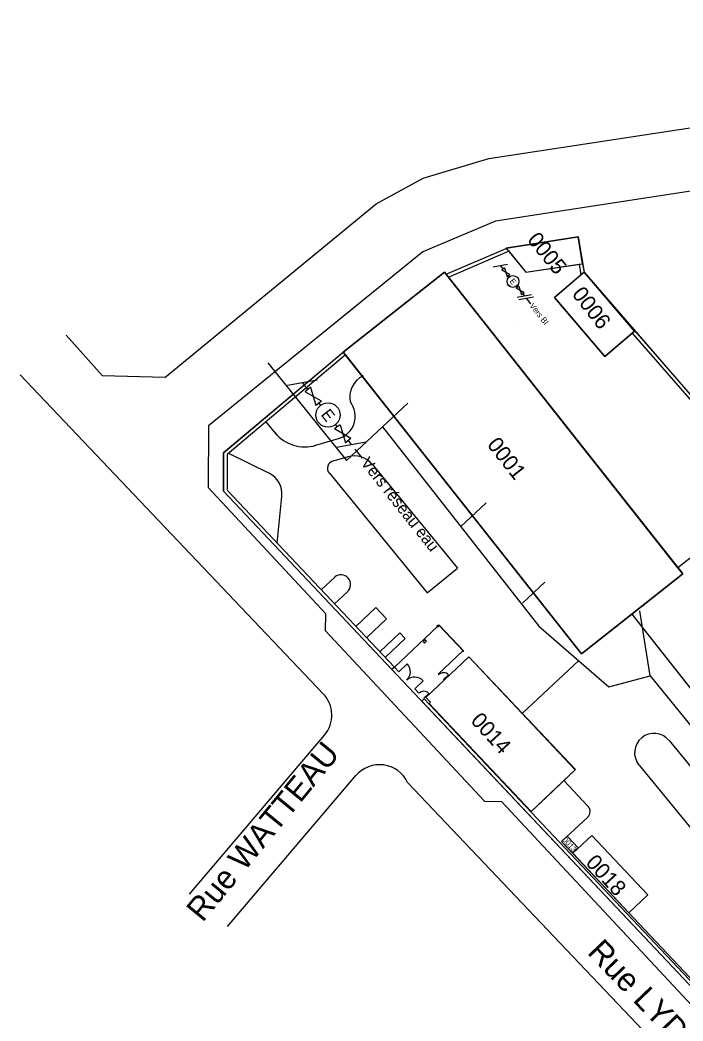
# Model space of a CAD drawing. Extents: x 703432 to 707394, y 7057985 to 7059523.
# Drawn here: x 704151.5 to 704236.8, y 7058728.3 to 7058857.2 of the extents above; entities that cross this region are included whole.
import ezdxf

# ---------------------------------------------------------------- set-up
doc = ezdxf.new("R2010")
doc.units = 0
for name, color, linetype in [('DH_HACHURE-MOTIF', 7, 'Continuous'), ('DH_TEXTE', 7, 'Continuous'), ('GO_MUR_EXTERIEUR', 7, 'Continuous'), ('IMM_LIMITE PHYSIQUE', 7, 'Continuous'), ('R_EPR_AEP_CANALISATION_CL_A', 7, 'Continuous'), ('R_PLU_CANALISATION_CL_A', 7, 'Continuous'), ('RES_EAU BASSE PRESSION', 7, 'Continuous'), ('RES_EAU BASSE PRESSION - EQUIP - TEXTE', 7, 'Continuous'), ('RES_INCENDIE - EQUIP - TEXTE', 7, 'Continuous'), ('SID_NUMERO_BATI', 7, 'Continuous'), ('SID_POLYLIGNES_BATI', 7, 'Continuous'), ('SID_POLYLIGNES_IMMEUBLE', 7, 'Continuous'), ('VOIRIE_BORDURE', 7, 'Continuous'), ('VOIRIE_ROUTE', 7, 'Continuous')]:
    doc.layers.add(name, color=color, linetype=linetype)

msp = doc.modelspace()

# ---------------------------------------------------------------- linework, layer by layer
at = {"layer": 'DH_HACHURE-MOTIF'}
for p, q in [((704220.3, 7058821.49), (704223.72, 7058824.42)), ((704223.72, 7058824.42), (704224.1, 7058824.74)), ((704224.1, 7058824.74), (704230.6, 7058817.15)), ((704226.8, 7058813.9), (704220.3, 7058821.49))]:
    msp.add_line(p, q, dxfattribs=at)
for points in [[(704223.47, 7058825.75), (704223.92, 7058825.82), (704223.34, 7058829.27), (704214.07, 7058827.84), (704214.4, 7058827.44), (704216.62, 7058824.72), (704223.47, 7058825.75)], [(704193.39, 7058814.1), (704195.59, 7058811.31), (704223.77, 7058775.59), (704230.25, 7058780.7), (704236.81, 7058785.87), (704236.19, 7058786.66), (704206.45, 7058824.35), (704206.14, 7058824.73), (704193.11, 7058814.45), (704193.39, 7058814.1)], [(704230.6, 7058817.15), (704230.26, 7058816.85), (704226.8, 7058813.9)], [(704282.57, 7058740.22), (704242.19, 7058791.4), (704236.19, 7058786.66), (704236.81, 7058785.87), (704230.25, 7058780.7), (704270.01, 7058730.31), (704282.57, 7058740.22)], [(704222.01, 7058752.02), (704221.94, 7058752.09), (704221.22, 7058751.41), (704222.64, 7058749.9), (704223.36, 7058750.59), (704222.01, 7058752.02)]]:
    msp.add_lwpolyline(points, dxfattribs=at)
for points in [[(704219.26, 7058757.12), (704222.98, 7058760.63), (704209.26, 7058775.18), (704203.74, 7058769.97), (704204.32, 7058769.36), (704204.15, 7058769.2), (704217.3, 7058755.27)], [(704225.09, 7058752.21), (704222.64, 7058749.9), (704229.88, 7058742.22), (704232.33, 7058744.54)]]:
    msp.add_lwpolyline(points, close=True, dxfattribs=at)
at = {"layer": 'GO_MUR_EXTERIEUR'}
for p, q in [((704223.34, 7058829.27), (704214.07, 7058827.84)), ((704223.92, 7058825.82), (704223.34, 7058829.27)), ((704214.07, 7058827.84), (704216.62, 7058824.72)), ((704216.62, 7058824.72), (704223.92, 7058825.82)), ((704193.11, 7058814.45), (704206.14, 7058824.73)), ((704206.14, 7058824.73), (704236.81, 7058785.87)), ((704224.1, 7058824.74), (704220.3, 7058821.49)), ((704230.6, 7058817.15), (704224.1, 7058824.74)), ((704220.3, 7058821.49), (704226.8, 7058813.9)), ((704220.3, 7058821.49), (704220.3, 7058821.49)), ((704226.8, 7058813.9), (704230.6, 7058817.15)), ((704223.77, 7058775.59), (704193.11, 7058814.45)), ((704242.19, 7058791.4), (704236.19, 7058786.66)), ((704236.19, 7058786.66), (704236.81, 7058785.87)), ((704236.81, 7058785.87), (704223.77, 7058775.59)), ((704236.81, 7058785.87), (704230.25, 7058780.7)), ((704230.25, 7058780.7), (704270.01, 7058730.31)), ((704209.29, 7058775.21), (704203.74, 7058769.97)), ((704223.02, 7058760.67), (704209.29, 7058775.21)), ((704217.3, 7058755.27), (704223.02, 7058760.67)), ((704221.22, 7058751.41), (704221.94, 7058752.09)), ((704221.94, 7058752.09), (704223.36, 7058750.59)), ((704222.64, 7058749.9), (704221.22, 7058751.41)), ((704223.36, 7058750.59), (704222.64, 7058749.9))]:
    msp.add_line(p, q, dxfattribs=at)
msp.add_lwpolyline([(704203.74, 7058769.97), (704204.32, 7058769.36), (704204.15, 7058769.2), (704217.3, 7058755.27)], dxfattribs=at)
msp.add_lwpolyline([(704225.09, 7058752.21), (704232.33, 7058744.54), (704229.88, 7058742.22), (704222.64, 7058749.9)], close=True, dxfattribs=at)
at = {"layer": 'IMM_LIMITE PHYSIQUE'}
for p, q in [((704206.36, 7058824.47), (704214.09, 7058827.8)), ((704206.66, 7058824.11), (704214.39, 7058827.45)), ((704223.47, 7058825.75), (704223.7, 7058824.4)), ((704223.92, 7058825.82), (704224.1, 7058824.74)), ((704230.31, 7058816.9), (704242.05, 7058803.37)), ((704230.65, 7058817.19), (704242.2, 7058803.87)), ((704193.12, 7058814.45), (704177.69, 7058801.47)), ((704193.4, 7058814.1), (704178.14, 7058801.27)), ((704177.69, 7058801.47), (704177.69, 7058796.52)), ((704178.14, 7058801.27), (704178.14, 7058796.73)), ((704177.69, 7058796.52), (704199.36, 7058773.55)), ((704178.16, 7058796.68), (704199.69, 7058773.86)), ((704199.69, 7058773.86), (704205.25, 7058779.11)), ((704205.34, 7058772.97), (704208.55, 7058776)), ((704199.69, 7058773.86), (704199.36, 7058773.55)), ((704199.69, 7058773.86), (704200.24, 7058773.28)), ((704200.24, 7058773.28), (704201.33, 7058774.3)), ((704205.34, 7058772.97), (704205.39, 7058772.91)), ((704206.67, 7058772.87), (704206.01, 7058772.26)), ((704206.01, 7058772.26), (704206.07, 7058772.19)), ((704202.3, 7058771.09), (704203.39, 7058772.12)), ((704202.3, 7058771.09), (704202.85, 7058770.51)), ((704203.53, 7058769.79), (704203.2, 7058769.48)), ((704204.12, 7058770.47), (704203.47, 7058769.86)), ((704203.47, 7058769.86), (704203.53, 7058769.79)), ((704203.53, 7058769.79), (704267.13, 7058702.37)), ((704203.2, 7058769.48), (704266.9, 7058701.96))]:
    msp.add_line(p, q, dxfattribs=at)
for points in [[(704205.41, 7058779.26), (704205.17, 7058779.2), (704205.33, 7058779.02)], [(704205.41, 7058779.26), (704208.57, 7058775.91), (704208.61, 7058775.94), (704205.45, 7058779.29)], [(704203.37, 7058777.19), (704203.58, 7058776.98), (704203.82, 7058777.2), (704203.62, 7058777.42)]]:
    msp.add_lwpolyline(points, close=True, dxfattribs=at)
for centre, radius, start, end in [((704200.24, 7058773.28), 1.5, 313.3307, 43.3307), ((704202.3, 7058771.09), 1.5, 43.3307, 133.3307), ((704206.01, 7058772.26), 0.9, 43.3307, 133.3307), ((704203.47, 7058769.86), 0.9, 43.3307, 133.3307)]:
    msp.add_arc(centre, radius, start, end, dxfattribs=at)
at = {"layer": 'R_EPR_AEP_CANALISATION_CL_A'}
for p, q in [((704183.39, 7058813.05), (704193.51, 7058800.5)), ((704198.15, 7058804.83), (704201.43, 7058807.89)), ((704193.51, 7058800.5), (704198.15, 7058804.83)), ((704198.15, 7058804.83), (704218.29, 7058779.15)), ((704208.22, 7058791.99), (704211.5, 7058795.05)), ((704216.18, 7058782.12), (704219.07, 7058784.82)), ((704232.63, 7058772.76), (704231.28, 7058781.12)), ((704216.16, 7058767.94), (704223.43, 7058774.72))]:
    msp.add_line(p, q, dxfattribs=at)
msp.add_lwpolyline([(704218.29, 7058779.15), (704227.29, 7058771.34), (704232.63, 7058772.76), (704273.17, 7058722.82)], dxfattribs=at)
at = {"layer": 'R_PLU_CANALISATION_CL_A'}
msp.add_circle((704214.95, 7058823.54), 0.76, dxfattribs=at)
at = {"layer": 'RES_EAU BASSE PRESSION'}
for p, q in [((704185.93, 7058810.19), (704189.75, 7058810.87)), ((704189.94, 7058807.86), (704190.18, 7058807.57)), ((704192.34, 7058804.83), (704192.11, 7058805.12)), ((704192.23, 7058802.21), (704196.05, 7058802.88)), ((704193.73, 7058803.06), (704194.14, 7058802.54))]:
    msp.add_line(p, q, dxfattribs=at)
at = {"layer": 'RES_EAU BASSE PRESSION - EQUIP - TEXTE'}
for p, q in [((704188.55, 7058809.63), (704187.84, 7058810.53)), ((704188.9, 7058809.91), (704188.2, 7058809.35)), ((704188.9, 7058809.91), (704189.59, 7058807.58)), ((704190.3, 7058808.14), (704188.2, 7058809.35)), ((704190.3, 7058808.14), (704189.59, 7058807.58)), ((704192.69, 7058805.1), (704191.99, 7058804.55)), ((704194.09, 7058803.34), (704191.99, 7058804.55)), ((704192.69, 7058805.1), (704193.38, 7058802.78)), ((704194.09, 7058803.34), (704193.38, 7058802.78)), ((704194.6, 7058801.95), (704195.53, 7058800.78))]:
    msp.add_line(p, q, dxfattribs=at)
msp.add_circle((704191.14, 7058806.34), 1.56, dxfattribs=at)
at = {"layer": 'RES_INCENDIE - EQUIP - TEXTE'}
for p, q in [((704212.4, 7058825.42), (704214.27, 7058825.75)), ((704213.68, 7058825.15), (704213.33, 7058825.59)), ((704213.85, 7058825.28), (704213.51, 7058825.01)), ((704213.85, 7058825.28), (704214.19, 7058824.15)), ((704214.54, 7058824.42), (704213.51, 7058825.01)), ((704214.54, 7058824.42), (704214.19, 7058824.15)), ((704214.36, 7058824.28), (704214.48, 7058824.14)), ((704215.71, 7058822.93), (704215.36, 7058822.66)), ((704216.39, 7058822.07), (704215.36, 7058822.66)), ((704215.53, 7058822.8), (704215.42, 7058822.94)), ((704215.71, 7058822.93), (704216.04, 7058821.8)), ((704215.48, 7058821.51), (704217.35, 7058821.85)), ((704215.71, 7058821.23), (704217.58, 7058821.56)), ((704216.39, 7058822.07), (704216.04, 7058821.8)), ((704216.22, 7058821.93), (704216.42, 7058821.68)), ((704216.64, 7058821.39), (704217.21, 7058820.67)), ((704215.49, 7058818.53), (704215.49, 7058818.53))]:
    msp.add_line(p, q, dxfattribs=at)
msp.add_circle((704214.95, 7058823.54), 0.763, dxfattribs=at)
at = {"layer": 'SID_POLYLIGNES_BATI'}
for p, q in [((704223.34, 7058829.27), (704214.07, 7058827.84)), ((704223.92, 7058825.82), (704223.34, 7058829.27)), ((704214.07, 7058827.84), (704216.62, 7058824.72)), ((704216.62, 7058824.72), (704223.92, 7058825.82)), ((704193.11, 7058814.45), (704206.14, 7058824.73)), ((704206.14, 7058824.73), (704236.81, 7058785.87)), ((704224.1, 7058824.74), (704220.3, 7058821.49)), ((704230.6, 7058817.15), (704224.1, 7058824.74)), ((704220.3, 7058821.49), (704226.8, 7058813.9)), ((704220.3, 7058821.49), (704220.3, 7058821.49)), ((704226.8, 7058813.9), (704230.6, 7058817.15)), ((704223.77, 7058775.59), (704193.11, 7058814.45)), ((704242.19, 7058791.4), (704236.19, 7058786.66)), ((704236.19, 7058786.66), (704236.81, 7058785.87)), ((704236.81, 7058785.87), (704223.77, 7058775.59)), ((704236.81, 7058785.87), (704230.25, 7058780.7)), ((704230.25, 7058780.7), (704270.01, 7058730.31)), ((704209.26, 7058775.18), (704203.74, 7058769.97)), ((704222.98, 7058760.63), (704209.26, 7058775.18)), ((704217.3, 7058755.27), (704222.98, 7058760.63)), ((704221.22, 7058751.41), (704221.94, 7058752.09)), ((704221.94, 7058752.09), (704223.36, 7058750.59)), ((704222.64, 7058749.9), (704221.22, 7058751.41)), ((704223.36, 7058750.59), (704222.64, 7058749.9))]:
    msp.add_line(p, q, dxfattribs=at)
msp.add_lwpolyline([(704203.74, 7058769.97), (704204.32, 7058769.36), (704204.15, 7058769.2), (704217.3, 7058755.27)], dxfattribs=at)
msp.add_lwpolyline([(704225.09, 7058752.21), (704232.33, 7058744.54), (704229.88, 7058742.22), (704222.64, 7058749.9)], close=True, dxfattribs=at)
at = {"layer": 'SID_POLYLIGNES_IMMEUBLE'}
for p, q in [((704177.69, 7058796.52), (704177.69, 7058801.47)), ((704266.9, 7058701.96), (704177.69, 7058796.52))]:
    msp.add_line(p, q, dxfattribs=at)
for points in [[(704206.14, 7058824.73), (704206.36, 7058824.47), (704214.09, 7058827.8), (704214.07, 7058827.84), (704223.34, 7058829.27)], [(704223.34, 7058829.27), (704224.1, 7058824.74), (704242.2, 7058803.87)], [(704177.69, 7058801.47), (704193.11, 7058814.45), (704206.14, 7058824.73)]]:
    msp.add_lwpolyline(points, dxfattribs=at)
at = {"layer": 'VOIRIE_BORDURE'}
for p, q in [((704183.15, 7058805.48), (704184.57, 7058803.75)), ((704189.57, 7058802.44), (704192.49, 7058803.3)), ((704188.83, 7058802.23), (704188.83, 7058802.23)), ((704178.33, 7058801.43), (704183.55, 7058798.85)), ((704191.79, 7058800.43), (704193.67, 7058800.97)), ((704196.83, 7058800), (704207.79, 7058786.61)), ((704191.31, 7058798.84), (704203.92, 7058783.44)), ((704184.61, 7058789.84), (704185.21, 7058795.87)), ((704203.92, 7058783.44), (704207.79, 7058786.61)), ((704190.27, 7058783.84), (704192.01, 7058785.48)), ((704191.99, 7058782.02), (704193.64, 7058783.59)), ((704194.73, 7058779.11), (704197.31, 7058781.55)), ((704198.69, 7058780.1), (704197.31, 7058781.55)), ((704196.1, 7058777.66), (704198.69, 7058780.1)), ((704197.82, 7058775.84), (704200.4, 7058778.28)), ((704198.51, 7058775.11), (704201.09, 7058777.55)), ((704201.09, 7058777.55), (704200.4, 7058778.28)), ((704235.05, 7058764.42), (704254.5, 7058740.69)), ((704231.18, 7058761.25), (704250.63, 7058737.52)), ((704221.52, 7058759.26), (704224.61, 7058755.98)), ((704224.57, 7058754.57), (704221.22, 7058751.41)), ((704221.22, 7058751.41), (704239.15, 7058732.4))]:
    msp.add_line(p, q, dxfattribs=at)
for centre, radius, start, end in [((704196.94, 7058808.67), 3, 115.4761, 192.4737), ((704191.65, 7058806.18), 3, 286.3025, 37.942), ((704188.17, 7058807.24), 5, 219.5679, 286.3025), ((704194.5, 7058798.09), 3, 39.3307, 106.0656), ((704192.07, 7058799.47), 1, 106.0656, 219.3307), ((704182.22, 7058796.16), 3, 354.3306, 63.7442), ((704192.8, 7058784.52), 1.25, 312.1096, 129.3307), ((704233.11, 7058762.84), 2.5, 39.3307, 219.3307), ((704223.89, 7058755.3), 1, 313.3306, 43.3306)]:
    msp.add_arc(centre, radius, start, end, dxfattribs=at)
at = {"layer": 'VOIRIE_ROUTE'}
for p, q in [((704190.52, 7058770.45), (704151.49, 7058811.52)), ((704170.12, 7058811.18), (704162.1, 7058811.38)), ((704175.74, 7058804.96), (704175.7, 7058797.01)), ((704175.7, 7058797.01), (704190.87, 7058780.75)), ((704190.81, 7058778.54), (704190.87, 7058780.75)), ((704190.81, 7058778.54), (704211.27, 7058756.61)), ((704173.29, 7058744.64), (704190.67, 7058765.11)), ((704178.22, 7058740.46), (704194.72, 7058759.9)), ((704258.1, 7058699.36), (704201.39, 7058759.02)), ((704211.27, 7058756.61), (704213.51, 7058756.55)), ((704213.46, 7058756.55), (704265.78, 7058700.48))]:
    msp.add_line(p, q, dxfattribs=at)
for points in [[(704170.12, 7058811.18), (704197.35, 7058833.54), (704203.38, 7058836.84), (704211.84, 7058839.38), (704328.73, 7058857.21)], [(704329.98, 7058849.33), (704212.69, 7058831.3), (704203.33, 7058827.34), (704175.74, 7058804.96)], [(704162.1, 7058811.38), (704157.43, 7058816.62)]]:
    msp.add_lwpolyline(points, dxfattribs=at)
for centre, start, end in [((704187.62, 7058767.7), 319.6675, 43.547), ((704197.77, 7058757.31), 25.2763, 139.6675)]:
    msp.add_arc(centre, 4, start, end, dxfattribs=at)

# ---------------------------------------------------------------- texts
at = {"layer": 'DH_TEXTE'}
for s, rotation, p in [('Rue WATTEAU', 50.7423, (704175, 7058740.91)), ('Rue LYDERIC', 313.8024, (704224.4, 7058737.04))]:
    msp.add_text(s, height=3, rotation=rotation, dxfattribs=at).set_placement(p)
at = {"layer": 'RES_EAU BASSE PRESSION - EQUIP - TEXTE'}
for s, p in [('E', (704190.15, 7058806.38)), ('Vers réseau eau', (704195.28, 7058800.16))]:
    msp.add_text(s, height=1.5, rotation=308.2727, dxfattribs=at).set_placement(p)
at = {"layer": 'RES_INCENDIE - EQUIP - TEXTE'}
for s, p in [('E', (704214.47, 7058823.56)), ('Vers BI', (704217.04, 7058820.4))]:
    msp.add_text(s, height=0.734, rotation=308.2727, dxfattribs=at).set_placement(p)
at = {"layer": 'SID_NUMERO_BATI'}
for s, height, rotation, p in [('0005', 2, 309.3307, (704216.7, 7058828.86)), ('0006', 2, 307.9879, (704222.46, 7058821.89)), ('0001', 2, 308.2727, (704211.53, 7058802.49)), ('0014', 2, 312.5129, (704209.4, 7058766.9)), ('0013', 0.698, 312.5129, (704221.26, 7058751.59)), ('0018', 2, 312.5129, (704224.21, 7058748.61))]:
    msp.add_text(s, height=height, rotation=rotation, dxfattribs=at).set_placement(p)

doc.saveas('drawing.dxf')
